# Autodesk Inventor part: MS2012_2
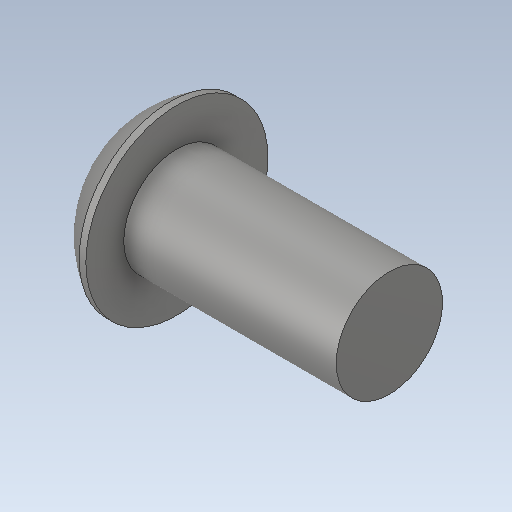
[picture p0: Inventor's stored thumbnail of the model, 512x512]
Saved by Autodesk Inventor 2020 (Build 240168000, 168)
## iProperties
Created: 2015-11
Part Number: MS2012_2
Material: Ogólny
Document SubType Name: Modeling
Designer: Tomasz
Density: 1 g/cm^3
Appearance: Domyślna
Sending System: SolidWorks 2017
Last Author: Tomasz
Last Saved: 2017-09-17
Author: Tomasz
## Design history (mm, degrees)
feature "Imported1"
node "Bryła1"
